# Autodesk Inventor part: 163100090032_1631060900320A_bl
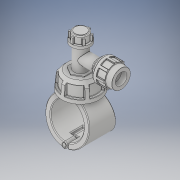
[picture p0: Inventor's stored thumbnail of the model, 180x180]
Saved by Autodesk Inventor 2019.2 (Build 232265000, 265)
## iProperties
Created: 2022-02
Part Number: 163100090032_1631060900320A_bl
Material: Generic
Description: Plassadle Tapper 90x32
Document SubType Name: Modeling
Designer: comp2
Density: 1 g/cm^3
Appearance: Default
Author: comp2
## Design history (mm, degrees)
derived "16310.ipt"
feature "Solid1::16310.ipt" dims "ScaleForDerivedMember" = 10
feature "Solid2::16310.ipt" dims "ScaleForDerivedMember" = 10
feature "Solid3::16310.ipt" dims "ScaleForDerivedMember" = 10
feature "Solid4::16310.ipt" dims "ScaleForDerivedMember" = 10
tag "TaggingFeature1"
body "Solid1"
body "Solid2"
body "Solid3"
body "Solid4"
other parameters: "d2" = 119 [user parameter], "d3" = 45 [user parameter], "d5" = 258 [user parameter], "d7" = 113.05 [user parameter], "d8" = 85 deg [user parameter], "d9" = 45 deg [user parameter], "d10" = 102 [user parameter], "d11" = 49 [user parameter], "d12" = 34.3 [user parameter], "d13" = 35.7 [user parameter], "d14" = 55.08 [user parameter], "d15" = 2.45 [user parameter], "d16" = 2 [user parameter], "d17" = 2 [user parameter], "d18" = 29.4 [user parameter], "d19" = 7.35 [user parameter], "d20" = 1 [user parameter], "d21" = 30.6 [user parameter], "d22" = 1 [user parameter], "d23" = 14.7 [user parameter], "d24" = 111 [user parameter], "d27" = 144 [user parameter], "d29" = 64 [user parameter], "d31" = 51.2 [user parameter], "d32" = 44.4 [user parameter], "d33" = 15.54 [user parameter], "d34" = 93 deg [user parameter], "d35" = 2 [user parameter], "d36" = 4 [user parameter], "d39" = 45 deg [user parameter], "d40" = 4 [user parameter], "d41" = 5 [user parameter], "d42" = 2.9 [user parameter], "d46" = 51 [user parameter], "d47" = 32 [user parameter], "d48" = 49 [user parameter], "d49" = 2.38 [user parameter], "d50" = 94 [user parameter], "d51" = 0 [user parameter], "d52" = 20.3 [user parameter], "d53" = 65.45 [user parameter], "d54" = 32.9 [user parameter], "d55" = 0 [user parameter], "d56" = 18.8 [user parameter], "d57" = 18.8 [user parameter], "d59" = 0 [user parameter], "d60" = 94 [user parameter], "d61" = 0 [user parameter], "d62" = 32.9 [user parameter], "d63" = 0 [user parameter], "d65" = 0 [user parameter], "d67" = 0 [user parameter], "d69" = 0 [user parameter], "d70" = 1 [user parameter], "d71" = 90.24 [user parameter], "d72" = 0 [user parameter], "d73" = 2 [user parameter], "d77" = 32 [user parameter], "d78" = 86.7 [user parameter], "d79" = 5.1 [user parameter], "d80" = 60 deg [user parameter], "d81" = 5.1 [user parameter], "d84" = 0 [user parameter], "d85" = 1 [user parameter], "d87" = 360 deg [user parameter], "d90" = 0 [user parameter], "d91" = 1 [user parameter], "d93" = 60 deg [user parameter], "d94" = 3.06 [user parameter], "d95" = 3.06 [user parameter], "d97" = 0 [user parameter], "d98" = 0.5 [user parameter], "d100" = 360 deg [user parameter], "d102" = 2 [user parameter], "d105" = 0 [user parameter], "d106" = 45 deg [user parameter], "d107" = 3.2 [user parameter], "d108" = 3.2 [user parameter], "d109" = 2.95332 [user parameter], "d110" = -8 [user parameter], "d112" = 0 [user parameter], "d113" = 0.5 [user parameter], "d115" = 360 deg [user parameter], "d117" = 0.5 [user parameter], "d1" = 32 [user parameter], "B" = 119 [user parameter], "L" = 94 [user parameter], "E_" = 64 [user parameter], "E1" = 102 [user parameter], "H1" = 258 [user parameter], "H2" = 144 [user parameter], "H3" = 111 [user parameter], "H_costum" = 49 [user parameter]
